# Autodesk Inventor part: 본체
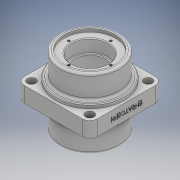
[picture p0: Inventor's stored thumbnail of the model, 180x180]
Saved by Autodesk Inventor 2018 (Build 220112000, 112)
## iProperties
Created: 2023-10
Part Number: 본체
Material: 일반
Document SubType Name: Modeling
Designer: home
Density: 1 g/cm^3
Appearance: 기본값
Author: home
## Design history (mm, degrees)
sketch "스케치1"
  geometry: L1 (-37, 47)-(37, 47); L2 (47, 37)-(47, -37); L3 (37, -47)-(-37, -47); L4 (-47, -37)-(-47, 37); A1 r 10 centre (-37, 37) between (-37, 47) and (-47, 37); A2 r 10 centre (37, 37) between (47, 37) and (37, 47); A3 r 10 centre (37, -37) between (37, -47) and (47, -37); A4 r 10 centre (-37, -37) between (-47, -37) and (-37, -47); 4 further points
  constraints: 8 end point, 8 point on circle, 8 tangent, 6 point on line, 4 centre point, 3 equal radius, 2 parallel, 1 horizontal, 1 perpendicular
  dimensions: "d0" = 94 distance of point (47, -47) point (-47, -47); "d1" = 94 distance of point (47, 47) point (47, -47); "d2" = 47 distance from line of point (0, 0) L1; "d3" = 47 distance from line of point (0, 0) L4; "d4" = 10 radius of A1
extrude "돌출1" new body sketch "스케치1" stored distance "d5" = 20; taper "d6" = 0 deg
sketch "스케치2"
  geometry: C1 r 38 at (0, 0); 1 further point
  constraints: 1 centre point, 1 coincident
  dimensions: "d7" = 76 diameter of C1
extrude "돌출2" join sketch "스케치2" stored distance "d8" = 90; taper "d9" = 0 deg
sketch "스케치3"
  geometry: C1 r 44 at (0, 0); 1 further point
  constraints: 1 centre point, 1 coincident
  dimensions: "d10" = 88 diameter of C1
extrude "돌출3" join sketch "스케치3" stored distance "d11" = 30; taper "d12" = 0 deg
sketch "스케치4"
  geometry: C1 r 33 at (0, 0); 1 further point
  constraints: 1 centre point, 1 coincident
  dimensions: "d13" = 66 diameter of C1
extrude "돌출4" cut sketch "스케치4" distance "d14" = 4; taper "d15" = 0 deg
sketch "스케치5"
  geometry: C1 r 23.5 at (0, 0); 1 further point
  constraints: 1 centre point, 1 coincident
  dimensions: "d16" = 47 diameter of C1
extrude "돌출5" cut sketch "스케치5" distance "d17" = 17; taper "d18" = 0 deg
sketch "스케치6"
  geometry: C1 r 20.5 at (0, 0); 1 further point
  constraints: 1 centre point, 1 coincident
  dimensions: "d19" = 41 diameter of C1
extrude "돌출6" cut sketch "스케치6" extent not by distance; stored distance "d20" = 17; taper "d21" = 0 deg
chamfer "모따기1" distance "d22" = 1; stored, may be unused: second distance "d23" = 2, angle "d24" = 45 deg
fillet "모깎기1" dims "d25" = 1
sketch "스케치7" dims "d26" = 54
  geometry: 3 further points
  constraints: 2 vertical alignment, 1 coincident, 2 other
hole "구멍1" sketch "스케치7" at (0, 27) diameter "d27" = 3.242; stored, may be unused: countersink angle "d31" = 90 deg, drill point angle "d33" = 118 deg; dims "d28" = 8, "d29" = 4, "d30" = 2, "d32" = 10
sketch "스케치8"
  geometry: L1 (0, 0)-(-53, 0); L2 (0, 0)-(-37.477, 37.477); C1 r 5.5 at (-37.477, 37.477); A1 r 53 centre (0, 0) between (-53, 0) and (-37.477, 37.477); 1 further point
  constraints: 4 end point, 2 centre point, 2 coincident, 2 point on circle, 1 horizontal
  dimensions: "d37" = 106 diameter of A1; "d38" = 45 deg angle of L1 L2; "d39" = 11 diameter of C1
extrude "돌출7" cut sketch "스케치8" distance "d40" = 7; taper "d41" = 0 deg
sketch "스케치9"
  geometry: C1 r 3.3 at (0, 0); 1 further point
  constraints: 1 centre point
  dimensions: "d42" = 6.6 diameter of C1; "d43" = 37.47666 horizontal distance of point (37.477, -37.477) C1.centre; "d44" = 37.47666 horizontal distance of point (37.477, -37.477) C1.centre
extrude "돌출8" cut sketch "스케치9" extent not by distance; stored distance "d45" = 7; taper "d46" = 0 deg
sketch "스케치10"
  geometry: C1 r 7 at (37, 10); 1 further point
  constraints: 1 centre point, 1 coincident
  dimensions: "d47" = 14 diameter of C1
extrude "돌출9" cut sketch "스케치10" distance "d48" = 2; taper "d49" = 0 deg
sketch "스케치11"
  geometry: C1 r 3.5 at (0, 0); 1 further point
  constraints: 1 centre point, 1 coincident
  dimensions: "d50" = 7 diameter of C1
extrude "돌출10" cut sketch "스케치11" distance "d51" = 2; taper "d52" = 0 deg
sketch "스케치12"
  geometry: 2 further points
  constraints: 1 coincident
hole "구멍2" sketch "스케치12" at (0, 0) diameter "d53" = 5.188; stored, may be unused: countersink angle "d57" = 90 deg, drill point angle "d59" = 118 deg; dims "d54" = 12, "d55" = 11, "d56" = 7, "d58" = 50
sketch "스케치13"
  geometry: 2 further points
  constraints: 1 coincident, 1 other
feature "엠보싱1" sketch "스케치13" dims "d0" = 94, "d1" = 94, "d2" = 47, "d3" = 47, "d4" = 10, "d60" = 0.5, "d61" = 0
fillet "모깎기2" dims "d62" = 3
chamfer "모따기2" distance "d63" = 1; stored, may be unused: second distance "d64" = 2, angle "d65" = 45 deg
node "솔리드1"
mirror "미러1"
pattern_circular "원형 패턴1" dims angle "d35" = 360 deg
mirror "미러2"
mirror "미러3"
mirror "미러4"
mirror "미러5"
